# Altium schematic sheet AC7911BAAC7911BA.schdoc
size 127 x 101 mm
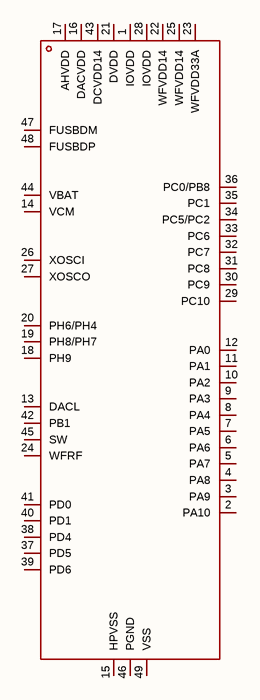
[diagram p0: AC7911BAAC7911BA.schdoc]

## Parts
U?  ac7911ba  [QFN-48_L6.0-W6.0-P0.40-TL-EP4.1]  (value not drawn)

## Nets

Not connected (* = marked no-connect by the designer): U? 1(IOVDD) 2(PA10) 3(PA9) 4(PA8) 5(PA7) 6(PA6) 7(PA5) 8(PA4) 9(PA3) 10(PA2) 11(PA1) 12(PA0) 13(DACL) 14(VCM) 15(HPVSS) 16(DACVDD) 17(AHVDD) 18(PH9) 19(PH8/PH7) 20(PH6/PH4) 21(DVDD) 22(WFVDD14) 23(WFVDD33A) 24(WFRF) 25(WFVDD14) 26(XOSCI) 27(XOSCO) 28(IOVDD) 29(PC10) 30(PC9) 31(PC8) 32(PC7) 33(PC6) 34(PC5/PC2) 35(PC1) 36(PC0/PB8) 37(PD5) 38(PD4) 39(PD6) 40(PD1) 41(PD0) 42(PB1) 43(DCVDD14) 44(VBAT) 45(SW) 46(PGND) 47(FUSBDM) 48(FUSBDP) 49(VSS)

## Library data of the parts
U? = ac7911ba: CPU内核:-;CPU最大主频:160MHz;CPU位数:32 Bit;; Manufacturer: JL(杰理); AddInBom: yes; ModelId: 899b9b118a1e4ef4b43b1bd995384417; ModelTransform: 237.007,237.007,0,0,0,0,0,0,0; CPU Maximum Speed: 160MHz; Core Size: 32 Bit; ADC (Bit): 16bit；10bit; DAC (Bit): 16bit; Voltage - Supply: 2V~5.5V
